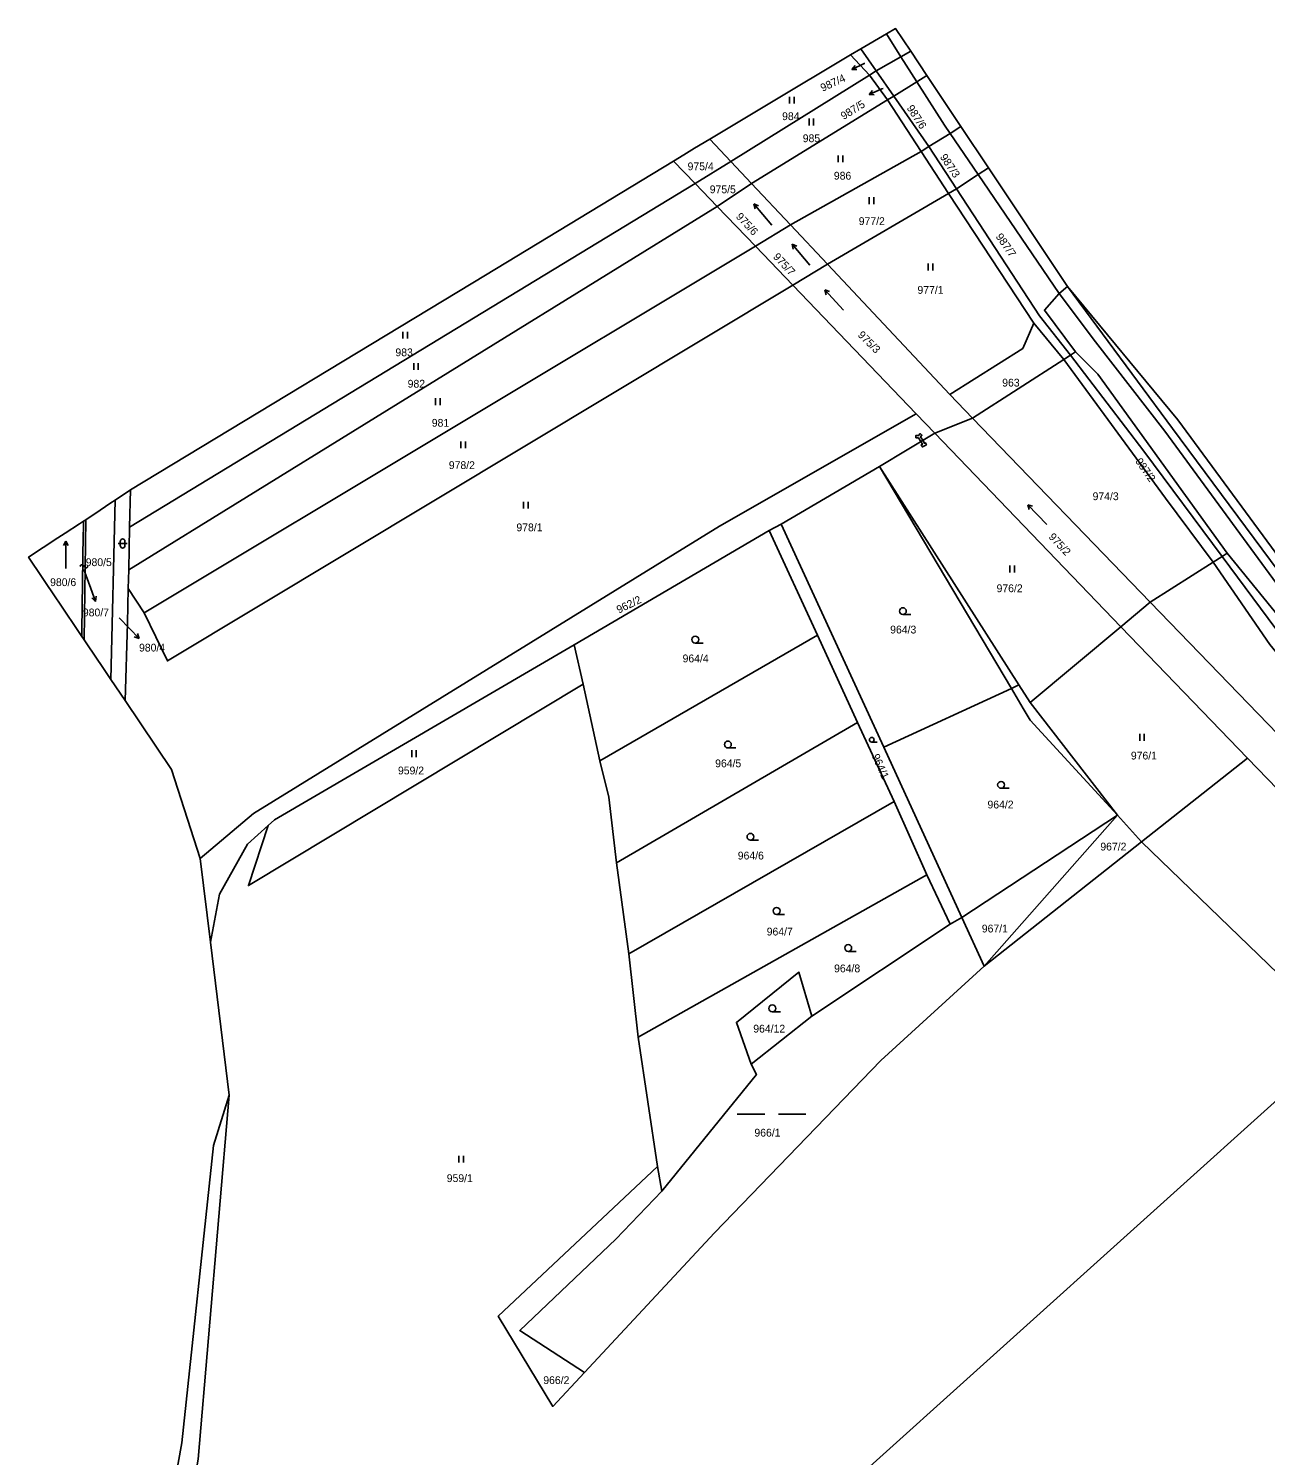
# Model space of a CAD drawing. Extents: x -757266 to -753360, y -1162585 to -1157740.
# Drawn here: x -756733.9 to -756464.1, y -1158051.1 to -1157740 of the extents above; entities that cross this region are included whole.
import ezdxf

# ---------------------------------------------------------------- set-up
doc = ezdxf.new("R2010")
doc.units = 0
for name, color, linetype in [('Hranice kat_území', 7, 'Continuous'), ('Hranice parcel', 7, 'Continuous'), ('Parcelní čísla', 7, 'Continuous'), ('Pop  PČ popisy', 7, 'Continuous'), ('Vnitřní kresba', 7, 'Continuous'), ('Věcná břemena k části', 7, 'Continuous'), ('Značky budov', 7, 'Continuous'), ('Značky kultur', 7, 'Continuous')]:
    doc.layers.add(name, color=color, linetype=linetype)

msp = doc.modelspace()

# ---------------------------------------------------------------- linework, layer by layer
at = {"layer": 'Hranice kat_území'}
msp.add_lwpolyline([(-756452.71, -1157866.81), (-756483.2, -1157825.33), (-756507.25, -1157796.25), (-756524.52, -1157770.37), (-756530.51, -1157761.4), (-756537.95, -1157750.26), (-756541.47, -1157744.99), (-756544.79, -1157740.02), (-756546.79, -1157741.19), (-756552.34, -1157744.44), (-756554.57, -1157745.74), (-756572.23, -1157756.29), (-756585.31, -1157764.14), (-756588.63, -1157766.14), (-756590.92, -1157767.55), (-756593.18, -1157768.92), (-756634.19, -1157793.76), (-756711.6, -1157840.59), (-756714.97, -1157842.86), (-756715.89, -1157843.47), (-756719.37, -1157845.8), (-756719.55, -1157845.92), (-756721.4, -1157847.12), (-756721.86, -1157847.42), (-756722.73, -1157847.99), (-756725.88, -1157850.05), (-756726.66, -1157850.56), (-756727.46, -1157851.08), (-756733.86, -1157855.26), (-756727.75, -1157864.34), (-756727.22, -1157865.12), (-756726.37, -1157866.4), (-756723.24, -1157871.06), (-756722.23, -1157872.56), (-756721.74, -1157873.29), (-756720.7, -1157874.83), (-756719.76, -1157876.22), (-756717.08, -1157880.2), (-756715.9, -1157881.96), (-756712.81, -1157886.56), (-756702.71, -1157901.57), (-756696.45, -1157920.96), (-756694.2, -1157939.24), (-756690.1, -1157972.6), (-756693.49, -1157983.54), (-756700.42, -1158048.42), (-756706.11, -1158079.84)], dxfattribs=at)
at = {"layer": 'Hranice parcel'}
for p, q in [((-756541.47, -1157744.99), (-756544.79, -1157740.02)), ((-756550.48, -1157750.17), (-756554.57, -1157745.74)), ((-756537.95, -1157750.26), (-756541.47, -1157744.99)), ((-756580.7, -1157769.04), (-756550.48, -1157750.17)), ((-756546.52, -1157755.59), (-756550.48, -1157750.17)), ((-756530.51, -1157761.4), (-756537.95, -1157750.26)), ((-756576.18, -1157773.84), (-756546.52, -1157755.59)), ((-756539.22, -1157766.86), (-756546.52, -1157755.59)), ((-756585.31, -1157764.14), (-756588.63, -1157766.14)), ((-756585.31, -1157764.14), (-756580.7, -1157769.04)), ((-756524.52, -1157770.37), (-756530.51, -1157761.4)), ((-756590.92, -1157767.55), (-756593.18, -1157768.92)), ((-756590.92, -1157767.55), (-756588.63, -1157766.14)), ((-756567.7, -1157782.85), (-756539.22, -1157766.86)), ((-756537.55, -1157765.72), (-756539.22, -1157766.86)), ((-756533.25, -1157775.96), (-756539.22, -1157766.86)), ((-756588.49, -1157773.8), (-756593.18, -1157768.92)), ((-756588.49, -1157773.8), (-756580.7, -1157769.04)), ((-756580.7, -1157769.04), (-756576.18, -1157773.84)), ((-756507.25, -1157796.25), (-756524.52, -1157770.37)), ((-756588.49, -1157773.8), (-756711.85, -1157848.73)), ((-756583.65, -1157778.84), (-756588.49, -1157773.8)), ((-756583.65, -1157778.84), (-756576.18, -1157773.84)), ((-756576.18, -1157773.84), (-756567.7, -1157782.85)), ((-756533.25, -1157775.96), (-756559.64, -1157791.42)), ((-756514.66, -1157804.29), (-756533.25, -1157775.96)), ((-756583.65, -1157778.84), (-756712.02, -1157858.02)), ((-756575.34, -1157787.5), (-756583.65, -1157778.84)), ((-756575.34, -1157787.5), (-756567.7, -1157782.85)), ((-756559.64, -1157791.42), (-756567.7, -1157782.85)), ((-756708.61, -1157867.45), (-756575.34, -1157787.5)), ((-756575.34, -1157787.5), (-756567.21, -1157795.97)), ((-756559.64, -1157791.42), (-756567.21, -1157795.97)), ((-756532.92, -1157819.8), (-756559.64, -1157791.42)), ((-756567.21, -1157795.97), (-756540.29, -1157824.02)), ((-756508.05, -1157812.15), (-756514.66, -1157804.29)), ((-756528.03, -1157825), (-756508.05, -1157812.15)), ((-756532.92, -1157819.8), (-756528.03, -1157825)), ((-756536.25, -1157828.23), (-756540.29, -1157824.02)), ((-756528.03, -1157825), (-756536.25, -1157828.23)), ((-756528.03, -1157825), (-756489.22, -1157865.1)), ((-756548.26, -1157835.52), (-756536.25, -1157828.23)), ((-756536.25, -1157828.23), (-756495.66, -1157870.49)), ((-756569.72, -1157848.06), (-756548.26, -1157835.52)), ((-756517.86, -1157883.14), (-756548.26, -1157835.52)), ((-756714.97, -1157842.86), (-756711.6, -1157840.59)), ((-756711.6, -1157840.59), (-756711.85, -1157848.73)), ((-756715.9, -1157881.96), (-756714.97, -1157842.86)), ((-756721.4, -1157847.12), (-756721.86, -1157847.42)), ((-756721.4, -1157847.12), (-756721.74, -1157873.29)), ((-756572.35, -1157849.45), (-756569.72, -1157848.06)), ((-756547.37, -1157896.71), (-756569.72, -1157848.06)), ((-756711.85, -1157848.73), (-756712.02, -1157858.02)), ((-756614.87, -1157874.42), (-756572.35, -1157849.45)), ((-756572.35, -1157849.45), (-756561.83, -1157872.26)), ((-756475.48, -1157856.35), (-756489.22, -1157865.1)), ((-756712.02, -1157858.02), (-756712.12, -1157862.09)), ((-756712.12, -1157862.09), (-756708.61, -1157867.45)), ((-756489.22, -1157865.1), (-756495.66, -1157870.49)), ((-756489.22, -1157865.1), (-756420.53, -1157936.28)), ((-756722.23, -1157872.56), (-756721.74, -1157873.29)), ((-756609.3, -1157899.71), (-756561.83, -1157872.26)), ((-756561.83, -1157872.26), (-756553.09, -1157891.33)), ((-756495.66, -1157870.49), (-756515.4, -1157886.99)), ((-756495.66, -1157870.49), (-756468.05, -1157899.08)), ((-756614.87, -1157874.42), (-756612.92, -1157883)), ((-756712.81, -1157886.56), (-756715.9, -1157881.96)), ((-756612.92, -1157883), (-756609.3, -1157899.71)), ((-756515.4, -1157886.99), (-756517.86, -1157883.14)), ((-756496.37, -1157911.55), (-756515.4, -1157886.99)), ((-756605.61, -1157921.9), (-756553.09, -1157891.33)), ((-756553.09, -1157891.33), (-756545.1, -1157908.59)), ((-756530.31, -1157933.84), (-756547.37, -1157896.71)), ((-756491.12, -1157917.32), (-756468.05, -1157899.08)), ((-756468.05, -1157899.08), (-756426.66, -1157941.95)), ((-756602.97, -1157941.75), (-756545.1, -1157908.59)), ((-756545.1, -1157908.59), (-756537.99, -1157924.55)), ((-756530.31, -1157933.84), (-756496.37, -1157911.55)), ((-756525.44, -1157944.45), (-756496.37, -1157911.55)), ((-756491.12, -1157917.32), (-756496.37, -1157911.55)), ((-756525.44, -1157944.45), (-756491.12, -1157917.32)), ((-756446.78, -1157960.25), (-756491.12, -1157917.32)), ((-756694.2, -1157939.24), (-756696.45, -1157920.96)), ((-756605.61, -1157921.9), (-756602.97, -1157941.75)), ((-756600.89, -1157959.93), (-756537.99, -1157924.55)), ((-756537.99, -1157924.55), (-756532.88, -1157935.29)), ((-756563.03, -1157955.34), (-756532.88, -1157935.29)), ((-756532.88, -1157935.29), (-756530.31, -1157933.84)), ((-756530.31, -1157933.84), (-756525.44, -1157944.45)), ((-756694.2, -1157939.24), (-756690.1, -1157972.6)), ((-756602.97, -1157941.75), (-756600.89, -1157959.93)), ((-756576.3, -1157965.85), (-756563.03, -1157955.34)), ((-756600.89, -1157959.93), (-756596.7, -1157988.18)), ((-756591.22, -1158090.24), (-756446.78, -1157960.25)), ((-756693.49, -1157983.54), (-756690.1, -1157972.6)), ((-756596.7, -1157988.18), (-756595.77, -1157993.51))]:
    msp.add_line(p, q, dxfattribs=at)
for points in [[(-756544.79, -1157740.02), (-756546.79, -1157741.19), (-756552.34, -1157744.44), (-756554.57, -1157745.74)], [(-756585.31, -1157764.14), (-756572.23, -1157756.29), (-756554.57, -1157745.74)], [(-756550.48, -1157750.17), (-756549.01, -1157749.23), (-756543.63, -1157746.22), (-756541.47, -1157744.99)], [(-756546.52, -1157755.59), (-756545.18, -1157754.74), (-756540.17, -1157751.63), (-756537.95, -1157750.26)], [(-756530.51, -1157761.4), (-756532.9, -1157762.87), (-756537.55, -1157765.72)], [(-756711.6, -1157840.59), (-756634.19, -1157793.76), (-756593.18, -1157768.92)], [(-756533.25, -1157775.96), (-756531.51, -1157774.94), (-756526.77, -1157771.84), (-756524.52, -1157770.37)], [(-756567.21, -1157795.97), (-756703.56, -1157877.91), (-756708.61, -1157867.45)], [(-756507.25, -1157796.25), (-756509.07, -1157797.78), (-756512.31, -1157801.46), (-756505.53, -1157810.53)], [(-756360.26, -1157972.38), (-756423.98, -1157904.58), (-756441.39, -1157884.82), (-756454.21, -1157867.88), (-756484.39, -1157827.24), (-756507.25, -1157796.25)], [(-756452.71, -1157866.81), (-756483.2, -1157825.33), (-756507.25, -1157796.25)], [(-756514.66, -1157804.29), (-756517.04, -1157809.81), (-756532.92, -1157819.8)], [(-756505.53, -1157810.53), (-756506.64, -1157811.25), (-756508.05, -1157812.15)], [(-756505.53, -1157810.53), (-756500.64, -1157815.35), (-756472.43, -1157854.4)], [(-756475.48, -1157856.35), (-756485.9, -1157842.4), (-756508.05, -1157812.15)], [(-756540.29, -1157824.02), (-756583.16, -1157848.53), (-756684.79, -1157911.16), (-756696.45, -1157920.96)], [(-756714.97, -1157842.86), (-756715.89, -1157843.47), (-756719.37, -1157845.8), (-756719.55, -1157845.92), (-756721.4, -1157847.12)], [(-756722.23, -1157872.56), (-756723.24, -1157871.06), (-756726.37, -1157866.4), (-756727.22, -1157865.12), (-756727.75, -1157864.34), (-756733.86, -1157855.26), (-756727.46, -1157851.08), (-756726.66, -1157850.56), (-756725.88, -1157850.05), (-756722.73, -1157847.99), (-756721.86, -1157847.42)], [(-756722.23, -1157872.56), (-756722.21, -1157871.27), (-756721.93, -1157850.26), (-756721.88, -1157849.28), (-756721.86, -1157847.42)], [(-756475.48, -1157856.35), (-756473.56, -1157855.13), (-756472.43, -1157854.4)], [(-756472.43, -1157854.4), (-756445.9, -1157886.95), (-756411.13, -1157927.58), (-756414.03, -1157930.26)], [(-756414.03, -1157930.26), (-756419.1, -1157925.03), (-756450.85, -1157889.29), (-756463.14, -1157874.29), (-756475.48, -1157856.35)], [(-756712.12, -1157862.09), (-756712.31, -1157869.67), (-756712.81, -1157886.56)], [(-756715.9, -1157881.96), (-756717.08, -1157880.2), (-756719.76, -1157876.22), (-756720.7, -1157874.83), (-756721.74, -1157873.29)], [(-756681.61, -1157913.8), (-756680.24, -1157912.57), (-756614.87, -1157874.42)], [(-756612.92, -1157883), (-756685.91, -1157926.91), (-756681.61, -1157913.8)], [(-756517.86, -1157883.14), (-756519.52, -1157883.91), (-756547.37, -1157896.71)], [(-756712.81, -1157886.56), (-756702.71, -1157901.57), (-756696.45, -1157920.96)], [(-756609.3, -1157899.71), (-756607.29, -1157907.58), (-756605.61, -1157921.9)], [(-756694.2, -1157939.24), (-756692.21, -1157928.79), (-756686.14, -1157917.87), (-756681.61, -1157913.8)], [(-756525.44, -1157944.45), (-756547.99, -1157965.02), (-756584.28, -1158002.64), (-756612.63, -1158033.04)], [(-756576.3, -1157965.85), (-756579.48, -1157956.73), (-756565.87, -1157945.8), (-756563.03, -1157955.34)], [(-756595.77, -1157993.51), (-756575.11, -1157968.09), (-756576.3, -1157965.85)], [(-756701.73, -1158079.89), (-756696.88, -1158051.96), (-756690.1, -1157972.6)], [(-756718.86, -1158113.37), (-756706.11, -1158079.84), (-756700.42, -1158048.42), (-756693.49, -1157983.54)], [(-756612.63, -1158033.04), (-756619.54, -1158040.44), (-756631.42, -1158020.81), (-756596.7, -1157988.18)], [(-756595.77, -1157993.51), (-756605.76, -1158004.01), (-756626.74, -1158023.9), (-756612.63, -1158033.04)]]:
    msp.add_lwpolyline(points, dxfattribs=at)
at = {"layer": 'Pop  PČ popisy'}
for p, q in [((-756551.6, -1157747.67), (-756554.32, -1157748.938)), ((-756554.32, -1157748.938), (-756553.624, -1157748.061)), ((-756554.32, -1157748.938), (-756553.201, -1157748.969)), ((-756551.47, -1157747.61), (-756551.6, -1157747.67)), ((-756547.79, -1157753.2), (-756550.532, -1157754.421)), ((-756550.532, -1157754.421), (-756549.82, -1157753.556)), ((-756550.532, -1157754.421), (-756549.413, -1157754.471)), ((-756547.49, -1157753.06), (-756547.79, -1157753.2)), ((-756721.77, -1157857.96), (-756720.28, -1157862.11)), ((-756720.28, -1157862.11), (-756719.254, -1157864.93)), ((-756719.254, -1157864.93), (-756719.126, -1157863.818)), ((-756719.254, -1157864.93), (-756720.067, -1157864.16)), ((-756714.1, -1157868.53), (-756711.85, -1157870.86)), ((-756711.85, -1157870.86), (-756709.765, -1157873.019)), ((-756709.765, -1157873.019), (-756710.821, -1157872.646)), ((-756709.765, -1157873.019), (-756710.101, -1157871.95))]:
    msp.add_line(p, q, dxfattribs=at)
at = {"layer": 'Vnitřní kresba'}
for p, q in [((-756546.79, -1157741.19), (-756543.63, -1157746.22)), ((-756552.34, -1157744.44), (-756549.01, -1157749.23)), ((-756543.63, -1157746.22), (-756540.17, -1157751.63)), ((-756549.01, -1157749.23), (-756545.18, -1157754.74)), ((-756540.17, -1157751.63), (-756534.12, -1157761.09)), ((-756545.18, -1157754.74), (-756537.55, -1157765.72)), ((-756534.12, -1157761.09), (-756532.9, -1157762.87)), ((-756532.9, -1157762.87), (-756526.77, -1157771.84)), ((-756537.55, -1157765.72), (-756531.51, -1157774.94)), ((-756526.77, -1157771.84), (-756509.07, -1157797.78)), ((-756531.51, -1157774.94), (-756513.37, -1157802.66)), ((-756509.07, -1157797.78), (-756501.2, -1157808.31)), ((-756506.64, -1157811.25), (-756513.37, -1157802.66)), ((-756501.2, -1157808.31), (-756486.08, -1157827.82)), ((-756490.6, -1157832.17), (-756506.64, -1157811.25)), ((-756486.08, -1157827.82), (-756456.07, -1157868.77)), ((-756473.56, -1157855.13), (-756490.6, -1157832.17)), ((-756548.26, -1157835.52), (-756519.52, -1157883.91)), ((-756473.56, -1157855.13), (-756460.17, -1157873.17)), ((-756519.52, -1157883.91), (-756516.93, -1157888.28)), ((-756516.93, -1157888.28), (-756515.4, -1157890.86)), ((-756515.4, -1157890.86), (-756496.37, -1157911.55))]:
    msp.add_line(p, q, dxfattribs=at)
at = {"layer": 'Věcná břemena k části'}
for points in [[(-756540.37, -1157829.27), (-756539.79, -1157829.27), (-756539.24, -1157830.05), (-756538.81, -1157829.79), (-756539.34, -1157829.03), (-756539.02, -1157828.65), (-756539.4, -1157828.33), (-756539.77, -1157828.77), (-756540.37, -1157828.77)], [(-756538.81, -1157829.79), (-756539.24, -1157830.05), (-756538.93, -1157830.66), (-756539.16, -1157830.78), (-756538.93, -1157831.23), (-756538.04, -1157830.76), (-756538.27, -1157830.32), (-756538.49, -1157830.44)]]:
    msp.add_lwpolyline(points, close=True, dxfattribs=at)
at = {"layer": 'Značky budov'}
msp.add_line((-756721.84, -1157857.136), (-756721.64, -1157857.404), dxfattribs=at)
for centre, start, end in [((-756722.1839, -1157857.3285), 29.291361, 181.218875), ((-756721.2961, -1157857.2112), 209.291358, 1.218872)]:
    msp.add_arc(centre, 0.3937, start, end, dxfattribs=at)
at = {"layer": 'Značky kultur'}
for p, q in [((-756567.901, -1157756.39), (-756567.901, -1157754.89)), ((-756566.9, -1157756.39), (-756566.9, -1157754.89)), ((-756563.651, -1157761.13), (-756563.651, -1157759.63)), ((-756562.65, -1157761.13), (-756562.65, -1157759.63)), ((-756557.281, -1157769.18), (-756557.281, -1157767.68)), ((-756556.28, -1157769.18), (-756556.28, -1157767.68)), ((-756550.551, -1157778.32), (-756550.551, -1157776.82)), ((-756549.55, -1157778.32), (-756549.55, -1157776.82)), ((-756571.796, -1157782.869), (-756575.653, -1157778.273)), ((-756575.653, -1157778.273), (-756575.409, -1157779.344)), ((-756575.653, -1157778.273), (-756574.641, -1157778.699)), ((-756563.496, -1157791.649), (-756567.353, -1157787.053)), ((-756567.353, -1157787.053), (-756567.109, -1157788.124)), ((-756567.353, -1157787.053), (-756566.341, -1157787.479)), ((-756537.681, -1157792.75), (-756537.681, -1157791.25)), ((-756536.68, -1157792.75), (-756536.68, -1157791.25)), ((-756556.168, -1157801.461), (-756560.182, -1157797.002)), ((-756560.182, -1157797.002), (-756559.901, -1157798.064)), ((-756560.182, -1157797.002), (-756559.156, -1157797.393)), ((-756652.201, -1157807.62), (-756652.201, -1157806.12)), ((-756651.2, -1157807.62), (-756651.2, -1157806.12)), ((-756649.861, -1157814.47), (-756649.861, -1157812.97)), ((-756648.86, -1157814.47), (-756648.86, -1157812.97)), ((-756645.101, -1157822.15), (-756645.101, -1157820.65)), ((-756644.1, -1157822.15), (-756644.1, -1157820.65)), ((-756639.561, -1157831.55), (-756639.561, -1157830.05)), ((-756638.56, -1157831.55), (-756638.56, -1157830.05)), ((-756625.891, -1157844.69), (-756625.891, -1157843.19)), ((-756624.89, -1157844.69), (-756624.89, -1157843.19)), ((-756511.792, -1157848.16), (-756515.96, -1157843.844)), ((-756515.96, -1157843.844), (-756515.642, -1157844.895)), ((-756515.96, -1157843.844), (-756514.92, -1157844.198)), ((-756725.731, -1157851.763), (-756726.233, -1157852.74)), ((-756725.731, -1157857.763), (-756725.731, -1157851.763)), ((-756725.731, -1157851.763), (-756725.23, -1157852.74)), ((-756714.341, -1157852.291), (-756712.339, -1157852.291)), ((-756713.841, -1157851.791), (-756713.841, -1157852.792)), ((-756712.839, -1157852.792), (-756712.839, -1157851.791)), ((-756519.871, -1157858.62), (-756519.871, -1157857.12)), ((-756518.87, -1157858.62), (-756518.87, -1157857.12)), ((-756543.183, -1157867.8), (-756541.433, -1157867.8)), ((-756588.453, -1157874.01), (-756586.703, -1157874.01)), ((-756491.541, -1157895.3), (-756491.541, -1157893.8)), ((-756490.54, -1157895.3), (-756490.54, -1157893.8)), ((-756650.301, -1157898.86), (-756650.301, -1157897.36)), ((-756649.3, -1157898.86), (-756649.3, -1157897.36)), ((-756581.353, -1157896.88), (-756579.603, -1157896.88)), ((-756549.965, -1157895.6), (-756548.793, -1157895.6)), ((-756521.763, -1157905.68), (-756520.013, -1157905.68)), ((-756576.423, -1157917), (-756574.673, -1157917)), ((-756570.713, -1157933.17), (-756568.963, -1157933.17)), ((-756555.103, -1157941.24), (-756553.353, -1157941.24)), ((-756571.653, -1157954.42), (-756569.903, -1157954.42)), ((-756579.319, -1157976.75), (-756573.319, -1157976.75)), ((-756570.319, -1157976.75), (-756564.319, -1157976.75)), ((-756640.031, -1157987.29), (-756640.031, -1157985.79)), ((-756639.03, -1157987.29), (-756639.03, -1157985.79))]:
    msp.add_line(p, q, dxfattribs=at)
for centre, radius in [((-756543.1829, -1157867.0498), 0.75), ((-756588.4529, -1157873.2598), 0.75), ((-756549.9652, -1157895.0974), 0.5025), ((-756581.3529, -1157896.1298), 0.75), ((-756521.7629, -1157904.9298), 0.75), ((-756576.4229, -1157916.2498), 0.75), ((-756570.7129, -1157932.4198), 0.75), ((-756555.1029, -1157940.4898), 0.75), ((-756571.6529, -1157953.6698), 0.75)]:
    msp.add_circle(centre, radius, dxfattribs=at)
for centre, start, end in [((-756713.34, -1157851.7909), 0, 180), ((-756713.34, -1157852.7909), 180, 359.987886)]:
    msp.add_arc(centre, 0.5, start, end, dxfattribs=at)

# ---------------------------------------------------------------- texts
at = {"layer": 'Parcelní čísla'}
for s, rotation, p in [('987/4', 25, (-756560.679, -1157753.828)), ('987/5', 32, (-756556.084, -1157759.986)), ('987/6', 303, (-756542.422, -1157757.362)), ('987/3', 304, (-756535.184, -1157768.045)), ('975/6', 313, (-756579.721, -1157781.129)), ('987/7', 305, (-756523.026, -1157785.397)), ('975/7', 313, (-756571.611, -1157789.899)), ('975/3', 315, (-756553.141, -1157806.971)), ('987/2', 305, (-756492.596, -1157834.397)), ('975/2', 313, (-756511.521, -1157850.969)), ('962/2', 26, (-756605.127, -1157867.613)), ('964/1', 294, (-756549.986, -1157898.635))]:
    msp.add_text(s, height=1.7, rotation=rotation, dxfattribs=at).set_placement(p)
for s, p in [('984', (-756569.52, -1157759.99)), ('985', (-756565.02, -1157764.8)), ('975/4', (-756590.13, -1157770.92)), ('986', (-756558.23, -1157772.96)), ('975/5', (-756585.3, -1157775.93)), ('977/2', (-756552.81, -1157782.86)), ('977/1', (-756540, -1157797.86)), ('983', (-756653.85, -1157811.47)), ('982', (-756651.18, -1157818.32)), ('963', (-756521.52, -1157818.08)), ('981', (-756645.92, -1157826.84)), ('978/2', (-756642.2, -1157836.07)), ('974/3', (-756501.81, -1157842.85)), ('978/1', (-756627.46, -1157849.64)), ('980/5', (-756721.39, -1157857.23)), ('980/6', (-756729.15, -1157861.59)), ('976/2', (-756522.75, -1157862.92)), ('980/7', (-756722.008, -1157868.19)), ('964/3', (-756545.95, -1157871.92)), ('980/4', (-756709.76, -1157875.858)), ('964/4', (-756591.22, -1157878.21)), ('976/1', (-756493.46, -1157899.4)), ('959/2', (-756653.29, -1157902.65)), ('964/5', (-756584.12, -1157901.09)), ('964/2', (-756524.73, -1157910.07)), ('964/6', (-756579.19, -1157921.2)), ('967/2', (-756500.12, -1157919.24)), ('967/1', (-756525.97, -1157937.11)), ('964/7', (-756572.88, -1157937.77)), ('964/8', (-756558.18, -1157945.8)), ('964/12', (-756575.81, -1157958.94)), ('966/1', (-756575.56, -1157981.62)), ('959/1', (-756642.66, -1157991.54)), ('966/2', (-756621.6, -1158035.58))]:
    msp.add_text(s, height=1.7, dxfattribs=at).set_placement(p)

doc.saveas('drawing.dxf')
